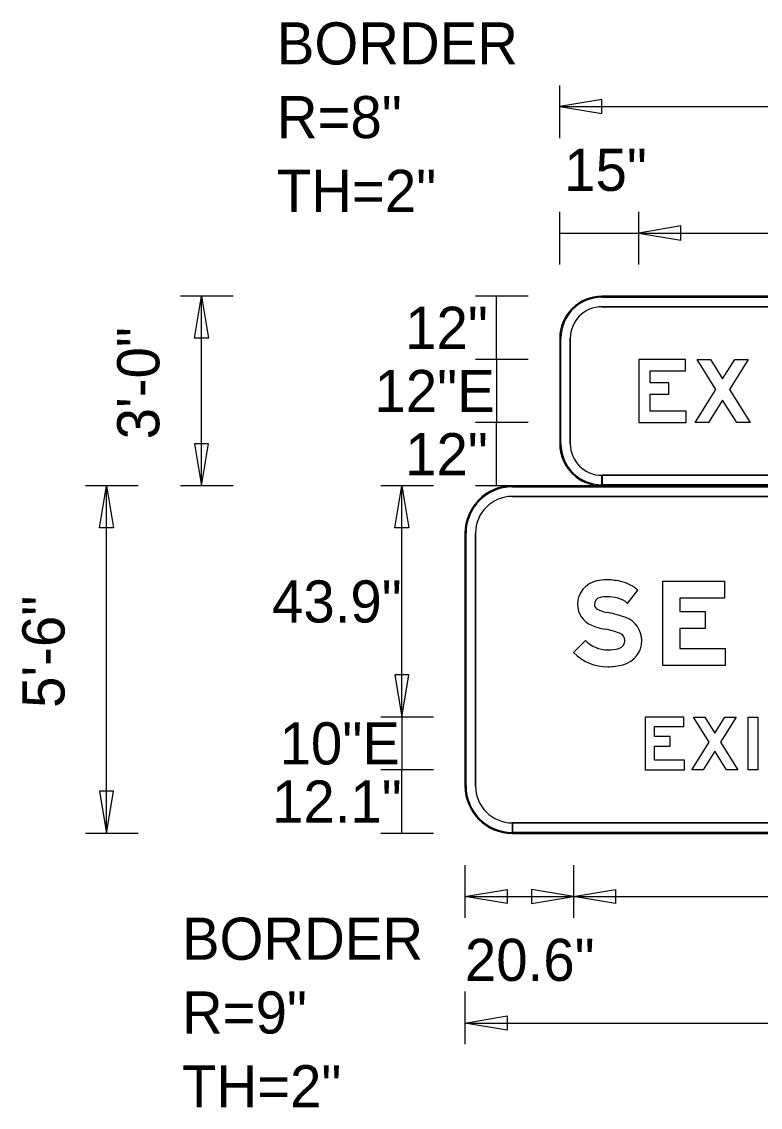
# Model space of a CAD drawing. Extents: x 2149961 to 2150220, y 145114 to 145240.
# Drawn here: x 2149974.07 to 2149985.74, y 145188.68 to 145205.85 of the extents above; entities that cross this region are included whole.
import ezdxf

# ---------------------------------------------------------------- set-up
doc = ezdxf.new("R2010")
doc.units = 0
for name, color, linetype in [('GSBWFILL', 7, 'Continuous'), ('GSCOLORFILL', 7, 'Continuous'), ('GSDIMS', 7, 'Continuous'), ('GSOUTLINE', 7, 'Continuous')]:
    doc.layers.add(name, color=color, linetype=linetype)

msp = doc.modelspace()

# ---------------------------------------------------------------- linework, layer by layer
at = {"layer": 'GSBWFILL'}
for p, q in [((2149994.908, 145201.509), (2149983.241, 145201.509)), ((2149983.241, 145201.343), (2149994.908, 145201.343)), ((2149982.575, 145200.843), (2149982.575, 145199.175)), ((2149982.741, 145199.175), (2149982.741, 145200.843)), ((2149983.241, 145198.509), (2149983.241, 145198.675)), ((2149994.908, 145198.675), (2149983.243, 145198.675)), ((2149983.243, 145198.675), (2149983.243, 145198.509)), ((2149994.825, 145198.509), (2149981.825, 145198.509)), ((2149983.243, 145198.509), (2149994.908, 145198.509)), ((2149981.825, 145198.342), (2149994.825, 145198.342)), ((2149981.075, 145197.759), (2149981.075, 145193.759)), ((2149981.242, 145193.759), (2149981.242, 145197.759)), ((2149981.825, 145193.009), (2149981.825, 145193.175)), ((2149994.825, 145193.175), (2149981.827, 145193.175)), ((2149981.827, 145193.175), (2149981.827, 145193.009)), ((2149981.827, 145193.009), (2149994.825, 145193.009))]:
    msp.add_line(p, q, dxfattribs=at)
for points in [[(2149984.575, 145199.689), (2149984.005, 145199.689), (2149984.005, 145199.958), (2149984.3, 145199.958), (2149984.3, 145200.138), (2149984.005, 145200.138), (2149984.005, 145200.329), (2149984.56, 145200.329), (2149984.56, 145200.509), (2149983.825, 145200.509), (2149983.825, 145199.509), (2149984.575, 145199.509)], [(2149985.372, 145199.509), (2149985.15, 145199.864), (2149984.927, 145199.509), (2149984.715, 145199.509), (2149985.044, 145200.033), (2149984.745, 145200.509), (2149984.957, 145200.509), (2149985.15, 145200.202), (2149985.342, 145200.509), (2149985.555, 145200.509), (2149985.256, 145200.033), (2149985.585, 145199.509)], [(2149985.178, 145197), (2149985.178, 145196.734), (2149984.472, 145196.734), (2149984.472, 145196.52), (2149984.872, 145196.52), (2149984.872, 145196.254), (2149984.472, 145196.254), (2149984.472, 145195.934), (2149985.192, 145195.934), (2149985.192, 145195.667), (2149984.205, 145195.667), (2149984.205, 145197)], [(2149984.547, 145194.167), (2149984.072, 145194.167), (2149984.072, 145194.391), (2149984.318, 145194.391), (2149984.318, 145194.541), (2149984.072, 145194.541), (2149984.072, 145194.7), (2149984.534, 145194.7), (2149984.534, 145194.85), (2149983.922, 145194.85), (2149983.922, 145194.017), (2149984.547, 145194.017)], [(2149985.211, 145194.017), (2149985.026, 145194.313), (2149984.841, 145194.017), (2149984.664, 145194.017), (2149984.937, 145194.454), (2149984.689, 145194.85), (2149984.866, 145194.85), (2149985.026, 145194.595), (2149985.186, 145194.85), (2149985.364, 145194.85), (2149985.115, 145194.454), (2149985.389, 145194.017)], [(2149985.555, 145194.017), (2149985.555, 145194.85), (2149985.705, 145194.85), (2149985.705, 145194.017)]]:
    msp.add_lwpolyline(points, close=True, dxfattribs=at)
for points in [[(2149983.645, 145196.649), (2149983.81, 145196.859)], [(2149982.979, 145196.059), (2149982.792, 145195.87)]]:
    msp.add_lwpolyline(points, dxfattribs=at)
for centre, radius, start, end in [((2149983.241, 145200.843), 0.667, 90, 180), ((2149983.241, 145200.843), 0.5, 90, 180), ((2149983.241, 145199.175), 0.667, 180, 270), ((2149983.241, 145199.175), 0.5, 180, 270), ((2149981.825, 145197.759), 0.75, 90, 180), ((2149981.825, 145197.759), 0.583, 90, 180), ((2149981.825, 145193.759), 0.75, 180, 270), ((2149981.825, 145193.759), 0.583, 180, 270)]:
    msp.add_arc(centre, radius, start, end, dxfattribs=at)
for centre, major_axis, start_param, end_param in [((2149983.237, 145196.631), (0, 0.382), 0.202758, 1.570796), ((2149983.318, 145196.236), (0, 0.785), 0, 0.202758), ((2149983.318, 145196.058), (0, 0.963), 6.026234, 6.283185), ((2149983.408, 145196.398), (0, 0.611), 5.565152, 6.026234), ((2149983.209, 145196.631), (0, 0.354), 1.570796, 2.761249), ((2149983.237, 145196.631), (0, 0.115), 0.202758, 1.570796), ((2149983.209, 145196.631), (0, 0.0872), 1.570796, 2.761249), ((2149983.318, 145196.236), (0, 0.519), 0, 0.202758), ((2149983.318, 145196.058), (0, 0.697), 6.026234, 6.283185), ((2149983.408, 145196.398), (0, 0.345), 5.523837, 6.026234), ((2149983.499, 145197.358), (0, 0.87), 2.761249, 2.95744), ((2149983.043, 145194.907), (0, 1.623), 5.918637, 6.099033), ((2149983.499, 145197.358), (0, 1.137), 2.761249, 2.95744), ((2149983.483, 145196.061), (0, 0.388), 4.712389, 5.918637), ((2149983.043, 145194.907), (0, 1.357), 5.918637, 6.099033), ((2149983.483, 145196.061), (0, 0.122), 4.712389, 5.918637), ((2149983.334, 145196.417), (0, 0.504), 2.360607, 3.141593), ((2149983.476, 145196.061), (0, 0.129), 3.401517, 4.712389), ((2149983.476, 145196.061), (0, 0.396), 3.401517, 4.712389), ((2149983.334, 145196.417), (0, 0.771), 2.360607, 3.141593), ((2149983.334, 145196.591), (0, 0.678), 3.141593, 3.401517), ((2149983.334, 145196.591), (0, 0.945), 3.141593, 3.401517)]:
    msp.add_ellipse(centre, major_axis=major_axis, ratio=0.999994, start_param=start_param, end_param=end_param, dxfattribs=at)
at = {"layer": 'GSCOLORFILL'}
for p, q in [((2149994.908, 145201.509), (2149983.241, 145201.509)), ((2149994.908, 145201.509), (2149983.241, 145201.509)), ((2149994.908, 145201.509), (2149983.241, 145201.509)), ((2149983.241, 145201.493), (2149994.908, 145201.493)), ((2149983.241, 145201.343), (2149994.908, 145201.343)), ((2149982.575, 145200.843), (2149982.575, 145199.175)), ((2149982.575, 145200.843), (2149982.575, 145199.175)), ((2149982.575, 145200.843), (2149982.575, 145199.175)), ((2149982.591, 145199.175), (2149982.591, 145200.843)), ((2149982.741, 145199.175), (2149982.741, 145200.843)), ((2149983.241, 145198.509), (2149983.241, 145198.675)), ((2149983.241, 145198.509), (2149983.241, 145198.525)), ((2149994.908, 145198.525), (2149983.242, 145198.525)), ((2149983.242, 145198.525), (2149983.242, 145198.509)), ((2149994.908, 145198.675), (2149983.243, 145198.675)), ((2149983.243, 145198.675), (2149983.243, 145198.509)), ((2149994.825, 145198.509), (2149981.825, 145198.509)), ((2149994.825, 145198.509), (2149981.825, 145198.509)), ((2149994.825, 145198.509), (2149981.825, 145198.509)), ((2149981.825, 145198.492), (2149994.825, 145198.492)), ((2149983.241, 145198.509), (2149994.908, 145198.509)), ((2149983.242, 145198.509), (2149994.908, 145198.509)), ((2149983.243, 145198.509), (2149994.908, 145198.509)), ((2149981.825, 145198.342), (2149994.825, 145198.342)), ((2149981.075, 145197.759), (2149981.075, 145193.759)), ((2149981.075, 145197.759), (2149981.075, 145193.759)), ((2149981.075, 145197.759), (2149981.075, 145193.759)), ((2149981.092, 145193.759), (2149981.092, 145197.759)), ((2149981.242, 145193.759), (2149981.242, 145197.759)), ((2149981.825, 145193.009), (2149981.825, 145193.175)), ((2149981.825, 145193.009), (2149981.825, 145193.025)), ((2149994.825, 145193.025), (2149981.825, 145193.025)), ((2149981.825, 145193.025), (2149981.825, 145193.009)), ((2149994.825, 145193.175), (2149981.827, 145193.175)), ((2149981.827, 145193.175), (2149981.827, 145193.009)), ((2149981.825, 145193.009), (2149994.825, 145193.009)), ((2149981.825, 145193.009), (2149994.825, 145193.009)), ((2149981.827, 145193.009), (2149994.825, 145193.009))]:
    msp.add_line(p, q, dxfattribs=at)
for points in [[(2149984.575, 145199.689), (2149984.005, 145199.689), (2149984.005, 145199.958), (2149984.3, 145199.958), (2149984.3, 145200.138), (2149984.005, 145200.138), (2149984.005, 145200.329), (2149984.56, 145200.329), (2149984.56, 145200.509), (2149983.825, 145200.509), (2149983.825, 145199.509), (2149984.575, 145199.509)], [(2149985.372, 145199.509), (2149985.15, 145199.864), (2149984.927, 145199.509), (2149984.715, 145199.509), (2149985.044, 145200.033), (2149984.745, 145200.509), (2149984.957, 145200.509), (2149985.15, 145200.202), (2149985.342, 145200.509), (2149985.555, 145200.509), (2149985.256, 145200.033), (2149985.585, 145199.509)], [(2149985.178, 145197), (2149985.178, 145196.734), (2149984.472, 145196.734), (2149984.472, 145196.52), (2149984.872, 145196.52), (2149984.872, 145196.254), (2149984.472, 145196.254), (2149984.472, 145195.934), (2149985.192, 145195.934), (2149985.192, 145195.667), (2149984.205, 145195.667), (2149984.205, 145197)], [(2149984.547, 145194.167), (2149984.072, 145194.167), (2149984.072, 145194.391), (2149984.318, 145194.391), (2149984.318, 145194.541), (2149984.072, 145194.541), (2149984.072, 145194.7), (2149984.534, 145194.7), (2149984.534, 145194.85), (2149983.922, 145194.85), (2149983.922, 145194.017), (2149984.547, 145194.017)], [(2149985.211, 145194.017), (2149985.026, 145194.313), (2149984.841, 145194.017), (2149984.664, 145194.017), (2149984.937, 145194.454), (2149984.689, 145194.85), (2149984.866, 145194.85), (2149985.026, 145194.595), (2149985.186, 145194.85), (2149985.364, 145194.85), (2149985.115, 145194.454), (2149985.389, 145194.017)], [(2149985.555, 145194.017), (2149985.555, 145194.85), (2149985.705, 145194.85), (2149985.705, 145194.017)]]:
    msp.add_lwpolyline(points, close=True, dxfattribs=at)
for points in [[(2149983.645, 145196.649), (2149983.81, 145196.859)], [(2149982.979, 145196.059), (2149982.792, 145195.87)]]:
    msp.add_lwpolyline(points, dxfattribs=at)
for centre, radius, start, end in [((2149983.241, 145200.843), 0.667, 90, 180), ((2149983.241, 145200.843), 0.667, 90, 180), ((2149983.241, 145200.843), 0.667, 90, 180), ((2149983.241, 145200.843), 0.65, 90, 180), ((2149983.241, 145200.843), 0.5, 90, 180), ((2149983.241, 145199.175), 0.667, 180, 270), ((2149983.241, 145199.175), 0.667, 180, 270), ((2149983.241, 145199.175), 0.667, 180, 270), ((2149983.241, 145199.175), 0.65, 180, 270), ((2149983.241, 145199.175), 0.5, 180, 270), ((2149981.825, 145197.759), 0.75, 90, 180), ((2149981.825, 145197.759), 0.75, 90, 180), ((2149981.825, 145197.759), 0.75, 90, 180), ((2149981.825, 145197.759), 0.733, 90, 180), ((2149981.825, 145197.759), 0.583, 90, 180), ((2149981.825, 145193.759), 0.75, 180, 270), ((2149981.825, 145193.759), 0.75, 180, 270), ((2149981.825, 145193.759), 0.75, 180, 270), ((2149981.825, 145193.759), 0.733, 180, 270), ((2149981.825, 145193.759), 0.583, 180, 270)]:
    msp.add_arc(centre, radius, start, end, dxfattribs=at)
for centre, major_axis, start_param, end_param in [((2149983.237, 145196.631), (0, 0.382), 0.202758, 1.570796), ((2149983.318, 145196.236), (0, 0.785), 0, 0.202758), ((2149983.318, 145196.058), (0, 0.963), 6.026234, 6.283185), ((2149983.408, 145196.398), (0, 0.611), 5.565152, 6.026234), ((2149983.209, 145196.631), (0, 0.354), 1.570796, 2.761249), ((2149983.237, 145196.631), (0, 0.115), 0.202758, 1.570796), ((2149983.209, 145196.631), (0, 0.0872), 1.570796, 2.761249), ((2149983.318, 145196.236), (0, 0.519), 0, 0.202758), ((2149983.318, 145196.058), (0, 0.697), 6.026234, 6.283185), ((2149983.408, 145196.398), (0, 0.345), 5.523837, 6.026234), ((2149983.499, 145197.358), (0, 0.87), 2.761249, 2.95744), ((2149983.043, 145194.907), (0, 1.623), 5.918637, 6.099033), ((2149983.499, 145197.358), (0, 1.137), 2.761249, 2.95744), ((2149983.483, 145196.061), (0, 0.388), 4.712389, 5.918637), ((2149983.043, 145194.907), (0, 1.357), 5.918637, 6.099033), ((2149983.483, 145196.061), (0, 0.122), 4.712389, 5.918637), ((2149983.334, 145196.417), (0, 0.504), 2.360607, 3.141593), ((2149983.476, 145196.061), (0, 0.129), 3.401517, 4.712389), ((2149983.476, 145196.061), (0, 0.396), 3.401517, 4.712389), ((2149983.334, 145196.417), (0, 0.771), 2.360607, 3.141593), ((2149983.334, 145196.591), (0, 0.678), 3.141593, 3.401517), ((2149983.334, 145196.591), (0, 0.945), 3.141593, 3.401517)]:
    msp.add_ellipse(centre, major_axis=major_axis, ratio=0.999994, start_param=start_param, end_param=end_param, dxfattribs=at)
at = {"layer": 'GSDIMS'}
for p, q in [((2149982.575, 145204.009), (2149982.575, 145204.843)), ((2149982.575, 145204.509), (2149995.575, 145204.509)), ((2149982.575, 145202.009), (2149982.575, 145202.843)), ((2149983.825, 145202.009), (2149983.825, 145202.843)), ((2149983.825, 145202.009), (2149983.825, 145202.843)), ((2149982.575, 145202.509), (2149983.825, 145202.509)), ((2149983.825, 145202.509), (2149994.325, 145202.509)), ((2149977.408, 145201.509), (2149976.575, 145201.509)), ((2149976.908, 145198.509), (2149976.908, 145201.509)), ((2149982.075, 145201.509), (2149981.241, 145201.509)), ((2149981.575, 145200.509), (2149981.575, 145201.509)), ((2149982.075, 145200.509), (2149981.241, 145200.509)), ((2149982.075, 145200.509), (2149981.241, 145200.509)), ((2149981.575, 145200.509), (2149981.575, 145199.509)), ((2149982.075, 145199.509), (2149981.241, 145199.509)), ((2149982.075, 145199.509), (2149981.241, 145199.509)), ((2149981.575, 145198.509), (2149981.575, 145199.509)), ((2149975.908, 145198.509), (2149975.075, 145198.509)), ((2149975.408, 145193.009), (2149975.408, 145198.509)), ((2149977.408, 145198.509), (2149976.575, 145198.509)), ((2149980.575, 145198.509), (2149979.742, 145198.509)), ((2149980.075, 145194.85), (2149980.075, 145198.509)), ((2149982.075, 145198.509), (2149981.241, 145198.509)), ((2149980.575, 145194.85), (2149979.742, 145194.85)), ((2149980.575, 145194.85), (2149979.742, 145194.85)), ((2149980.075, 145194.85), (2149980.075, 145194.017)), ((2149980.575, 145194.017), (2149979.742, 145194.017)), ((2149980.575, 145194.017), (2149979.742, 145194.017)), ((2149980.075, 145193.009), (2149980.075, 145194.017)), ((2149975.908, 145193.009), (2149975.075, 145193.009)), ((2149980.575, 145193.009), (2149979.742, 145193.009)), ((2149981.075, 145192.509), (2149981.075, 145191.675)), ((2149982.792, 145192.509), (2149982.792, 145191.675)), ((2149982.792, 145192.509), (2149982.792, 145191.675)), ((2149981.075, 145192.009), (2149982.792, 145192.009)), ((2149982.792, 145192.009), (2149993.858, 145192.009)), ((2149981.075, 145190.509), (2149981.075, 145189.675)), ((2149981.075, 145190.009), (2149995.575, 145190.009))]:
    msp.add_line(p, q, dxfattribs=at)
for points in [[(2149982.575, 145204.509), (2149983.241, 145204.398), (2149983.241, 145204.62)], [(2149983.825, 145202.509), (2149984.491, 145202.398), (2149984.491, 145202.621)], [(2149976.908, 145201.509), (2149977.019, 145200.843), (2149976.797, 145200.843)], [(2149976.908, 145198.509), (2149977.019, 145199.175), (2149976.797, 145199.175)], [(2149975.408, 145198.509), (2149975.519, 145197.842), (2149975.297, 145197.842)], [(2149980.075, 145198.509), (2149980.186, 145197.842), (2149979.964, 145197.842)], [(2149980.075, 145194.85), (2149980.186, 145195.517), (2149979.964, 145195.517)], [(2149975.408, 145193.009), (2149975.519, 145193.675), (2149975.297, 145193.675)], [(2149981.075, 145192.009), (2149981.742, 145192.12), (2149981.742, 145191.898)], [(2149982.792, 145192.009), (2149982.125, 145192.12), (2149982.125, 145191.898)], [(2149982.792, 145192.009), (2149983.458, 145192.12), (2149983.458, 145191.898)], [(2149981.075, 145190.009), (2149981.742, 145190.12), (2149981.742, 145189.898)]]:
    msp.add_lwpolyline(points, close=True, dxfattribs=at)
at = {"layer": 'GSOUTLINE'}
for p, q in [((2149994.908, 145201.509), (2149983.241, 145201.509)), ((2149994.908, 145201.343), (2149983.241, 145201.343)), ((2149982.575, 145200.843), (2149982.575, 145199.175)), ((2149982.741, 145200.843), (2149982.741, 145199.175)), ((2149983.241, 145198.675), (2149994.908, 145198.675)), ((2149994.825, 145198.509), (2149981.825, 145198.509)), ((2149983.241, 145198.509), (2149994.908, 145198.509)), ((2149994.825, 145198.342), (2149981.825, 145198.342)), ((2149981.075, 145197.759), (2149981.075, 145193.759)), ((2149981.242, 145197.759), (2149981.242, 145193.759)), ((2149981.825, 145193.175), (2149994.825, 145193.175)), ((2149981.825, 145193.009), (2149994.825, 145193.009))]:
    msp.add_line(p, q, dxfattribs=at)
for points in [[(2149984.575, 145199.689), (2149984.005, 145199.689), (2149984.005, 145199.958), (2149984.3, 145199.958), (2149984.3, 145200.138), (2149984.005, 145200.138), (2149984.005, 145200.329), (2149984.56, 145200.329), (2149984.56, 145200.509), (2149983.825, 145200.509), (2149983.825, 145199.509), (2149984.575, 145199.509)], [(2149985.372, 145199.509), (2149985.15, 145199.864), (2149984.927, 145199.509), (2149984.715, 145199.509), (2149985.044, 145200.033), (2149984.745, 145200.509), (2149984.957, 145200.509), (2149985.15, 145200.202), (2149985.342, 145200.509), (2149985.555, 145200.509), (2149985.256, 145200.033), (2149985.585, 145199.509)], [(2149985.178, 145197), (2149985.178, 145196.734), (2149984.472, 145196.734), (2149984.472, 145196.52), (2149984.872, 145196.52), (2149984.872, 145196.254), (2149984.472, 145196.254), (2149984.472, 145195.934), (2149985.192, 145195.934), (2149985.192, 145195.667), (2149984.205, 145195.667), (2149984.205, 145197)], [(2149984.547, 145194.167), (2149984.072, 145194.167), (2149984.072, 145194.391), (2149984.318, 145194.391), (2149984.318, 145194.541), (2149984.072, 145194.541), (2149984.072, 145194.7), (2149984.534, 145194.7), (2149984.534, 145194.85), (2149983.922, 145194.85), (2149983.922, 145194.017), (2149984.547, 145194.017)], [(2149985.211, 145194.017), (2149985.026, 145194.313), (2149984.841, 145194.017), (2149984.664, 145194.017), (2149984.937, 145194.454), (2149984.689, 145194.85), (2149984.866, 145194.85), (2149985.026, 145194.595), (2149985.186, 145194.85), (2149985.364, 145194.85), (2149985.115, 145194.454), (2149985.389, 145194.017)], [(2149985.555, 145194.017), (2149985.555, 145194.85), (2149985.705, 145194.85), (2149985.705, 145194.017)]]:
    msp.add_lwpolyline(points, close=True, dxfattribs=at)
for points in [[(2149983.645, 145196.649), (2149983.81, 145196.859)], [(2149982.979, 145196.059), (2149982.792, 145195.87)]]:
    msp.add_lwpolyline(points, dxfattribs=at)
for centre, radius, start, end in [((2149983.241, 145200.843), 0.667, 90, 180), ((2149983.241, 145200.843), 0.5, 90, 180), ((2149983.241, 145199.175), 0.667, 180, 270), ((2149983.241, 145199.175), 0.5, 180, 270), ((2149981.825, 145197.759), 0.75, 90, 180), ((2149981.825, 145197.759), 0.583, 90, 180), ((2149981.825, 145193.759), 0.75, 180, 270), ((2149981.825, 145193.759), 0.583, 180, 270)]:
    msp.add_arc(centre, radius, start, end, dxfattribs=at)
for centre, major_axis, start_param, end_param in [((2149983.237, 145196.631), (0, 0.382), 0.202758, 1.570796), ((2149983.318, 145196.236), (0, 0.785), 0, 0.202758), ((2149983.318, 145196.058), (0, 0.963), 6.026234, 6.283185), ((2149983.408, 145196.398), (0, 0.611), 5.565152, 6.026234), ((2149983.209, 145196.631), (0, 0.354), 1.570796, 2.761249), ((2149983.237, 145196.631), (0, 0.115), 0.202758, 1.570796), ((2149983.209, 145196.631), (0, 0.0872), 1.570796, 2.761249), ((2149983.318, 145196.236), (0, 0.519), 0, 0.202758), ((2149983.318, 145196.058), (0, 0.697), 6.026234, 6.283185), ((2149983.408, 145196.398), (0, 0.345), 5.523837, 6.026234), ((2149983.499, 145197.358), (0, 0.87), 2.761249, 2.95744), ((2149983.043, 145194.907), (0, 1.623), 5.918637, 6.099033), ((2149983.499, 145197.358), (0, 1.137), 2.761249, 2.95744), ((2149983.483, 145196.061), (0, 0.388), 4.712389, 5.918637), ((2149983.043, 145194.907), (0, 1.357), 5.918637, 6.099033), ((2149983.483, 145196.061), (0, 0.122), 4.712389, 5.918637), ((2149983.334, 145196.417), (0, 0.504), 2.360607, 3.141593), ((2149983.476, 145196.061), (0, 0.129), 3.401517, 4.712389), ((2149983.476, 145196.061), (0, 0.396), 3.401517, 4.712389), ((2149983.334, 145196.417), (0, 0.771), 2.360607, 3.141593), ((2149983.334, 145196.591), (0, 0.678), 3.141593, 3.401517), ((2149983.334, 145196.591), (0, 0.945), 3.141593, 3.401517)]:
    msp.add_ellipse(centre, major_axis=major_axis, ratio=0.999994, start_param=start_param, end_param=end_param, dxfattribs=at)

# ---------------------------------------------------------------- texts
at = {"layer": 'GSDIMS'}
for s, p in [('BORDER', (2149978.099, 145205.176)), ('R=8"', (2149978.099, 145204.01)), ('15"', (2149982.644, 145203.176)), ('TH=2"', (2149978.099, 145202.843)), ('12"', (2149980.129, 145200.676)), ('12"E', (2149979.643, 145199.676)), ('12"', (2149980.129, 145198.676)), ('43.9"', (2149978.023, 145196.346)), ('10"E', (2149978.143, 145194.1)), ('12.1"', (2149978.023, 145193.18)), ('BORDER', (2149976.599, 145191.009)), ('20.6"', (2149981.074, 145190.675)), ('R=9"', (2149976.599, 145189.842)), ('TH=2"', (2149976.599, 145188.675))]:
    msp.add_text(s, height=0.6667, dxfattribs=at).set_placement(p)
for s, p in [('3\'-0"', (2149976.241, 145199.245)), ('5\'-6"', (2149974.742, 145194.995))]:
    msp.add_text(s, height=0.6667, rotation=90, dxfattribs=at).set_placement(p)

doc.saveas('drawing.dxf')
